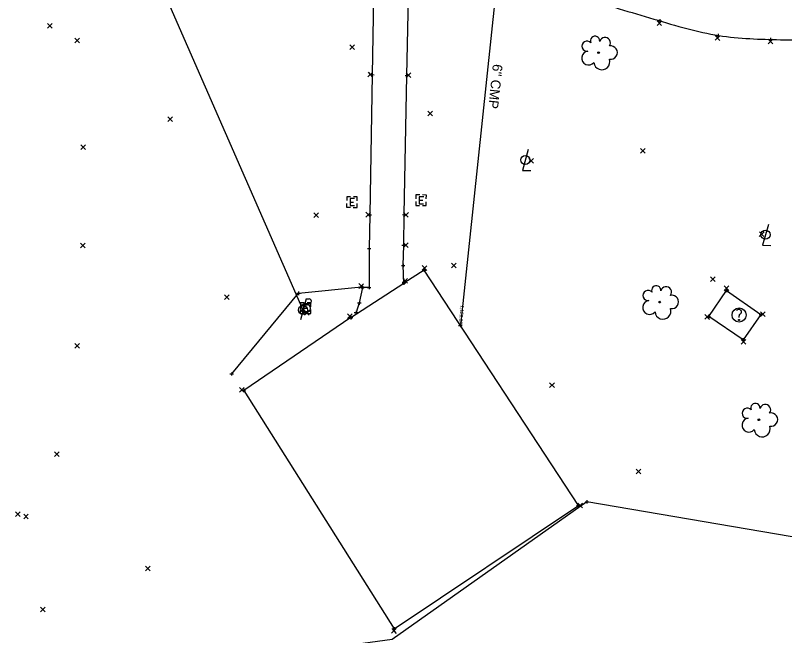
# Model space of a CAD drawing. Extents: x 142461 to 147261, y 511126 to 514697.
# Drawn here: x 144942.1 to 145161.9, y 512719.1 to 512896.1 of the extents above; entities that cross this region are included whole.
import ezdxf

# ---------------------------------------------------------------- set-up
doc = ezdxf.new("R2010")
doc.units = 0
for name, color, linetype in [('DR_X_Elev_Flow', 7, 'Continuous'), ('GT_X_Rock_Outcrop', 7, 'Continuous'), ('LT_X_Poles', 7, 'Continuous'), ('PV_X_Walk', 7, 'Continuous'), ('RD_X_Concrete_Pad', 7, 'Continuous'), ('RD_X_Fence', 7, 'Continuous'), ('RD_X_Gate', 7, 'Continuous'), ('RD_X_Misc_Items', 7, 'Continuous'), ('SC_Scratch1', 7, 'Continuous'), ('SV_X_Random_Point', 7, 'Continuous'), ('SV_X_Shot_Marker', 7, 'Continuous'), ('UT_X_Electric', 7, 'Continuous'), ('UT_X_Electric_Cells', 7, 'Continuous'), ('UT_X_Sanitary_Line', 7, 'Continuous'), ('UT_X_Sanitary_Text', 7, 'Continuous'), ('VG_X_Cells', 7, 'Continuous'), ('VG_X_Tree_Line_Rt', 7, 'Continuous')]:
    doc.layers.add(name, color=color, linetype=linetype)

msp = doc.modelspace()

# ---------------------------------------------------------------- linework, layer by layer
at = {"layer": 'DR_X_Elev_Flow'}
for p, q in [((145069.22, 512808.09), (145069.22, 512807.09)), ((145068.72, 512807.59), (145069.72, 512807.59)), ((145069.22, 512807.59), (145069.22, 512807.59))]:
    msp.add_line(p, q, dxfattribs=at)
at = {"layer": 'GT_X_Rock_Outcrop'}
msp.add_lwpolyline([(145003.89, 512793.77), (145023.02, 512816.77), (145041.01, 512818.64)], dxfattribs=at)
at = {"layer": 'LT_X_Poles'}
for points in [[(145088.61, 512857.79), (145086.97, 512851.82), (145089.34, 512851.8)], [(145157.21, 512836.44), (145155.58, 512830.48), (145157.94, 512830.45)]]:
    msp.add_lwpolyline(points, dxfattribs=at)
for centre in [(145087.79, 512854.84), (145156.4, 512833.5)]:
    msp.add_circle(centre, 1.3, dxfattribs=at)
at = {"layer": 'PV_X_Walk'}
for p, q in [((145044.7, 512919.18), (145044.06, 512879.19)), ((145053.92, 512878.99), (145054.78, 512918.79)), ((145044.06, 512879.19), (145043.35, 512839.22)), ((145053.18, 512839.23), (145053.92, 512878.99)), ((145043.35, 512839.22), (145043.15, 512829.53)), ((145053.03, 512830.54), (145053.18, 512839.23)), ((145052.88, 512824.7), (145053.03, 512830.54)), ((145043.15, 512829.53), (145043.14, 512818.41)), ((145053.1, 512819.92), (145052.88, 512824.7)), ((145041.24, 512818.45), (145040.36, 512814.02)), ((145043.14, 512818.41), (145041.24, 512818.45)), ((145040.36, 512814.02), (145039.41, 512811.27))]:
    msp.add_line(p, q, dxfattribs=at)
msp.add_open_spline([(145063.98, 512925.11), (145069.77, 512919.92), (145080.69, 512909.67), (145103.07, 512901.33), (145123.63, 512895.37), (145142.03, 512889.72), (145159.63, 512889.13), (145176.81, 512888.85), (145194, 512889.65), (145209.87, 512893.18), (145224.9, 512894.34), (145240.29, 512892.09), (145248.15, 512887), (145251.76, 512882.95)], degree=3, dxfattribs=at)
at = {"layer": 'RD_X_Concrete_Pad'}
msp.add_lwpolyline([(145140.22, 512810.19), (145145.29, 512817.62), (145155.1, 512810.72), (145150.05, 512803.47)], close=True, dxfattribs=at)
at = {"layer": 'RD_X_Fence'}
msp.add_lwpolyline([(145037.96, 512809.83), (145007.33, 512789.05), (145050.33, 512720.98), (145102.93, 512756.21), (145058.85, 512823.41), (145053.07, 512819.65)], dxfattribs=at)
at = {"layer": 'RD_X_Gate'}
msp.add_lwpolyline([(145037.96, 512809.83), (145053.07, 512819.65)], dxfattribs=at)
at = {"layer": 'RD_X_Misc_Items'}
msp.add_line((145148.83, 512809.82), (145148.83, 512810.3), dxfattribs=at)
for centre, radius in [((145148.84, 512810.58), 2), ((145148.82, 512809.17), 0.17)]:
    msp.add_circle(centre, radius, dxfattribs=at)
for centre, radius, start, end in [((145148.78, 512811.39), 0.754, 87.7326, 151.9471), ((145148.83, 512811.46), 0.688, 291.3416, 91.867), ((145149.42, 512810.34), 0.587, 124.8704, 183.4915)]:
    msp.add_arc(centre, radius, start, end, dxfattribs=at)
at = {"layer": 'SV_X_Random_Point'}
for p, q in [((144951.24, 512892.43), (144952.57, 512893.76)), ((144951.24, 512893.76), (144952.57, 512892.43)), ((145125.4, 512893.26), (145126.75, 512894.58)), ((145125.42, 512894.59), (145126.73, 512893.24)), ((144959.06, 512888.25), (144960.4, 512889.59)), ((144959.06, 512889.59), (144960.4, 512888.25)), ((145142.05, 512888.99), (145143.39, 512890.31)), ((145142.06, 512890.32), (145143.38, 512888.97)), ((145157.18, 512887.98), (145158.52, 512889.3)), ((145157.19, 512889.31), (145158.51, 512887.96)), ((145037.68, 512886.39), (145039.02, 512887.72)), ((145037.68, 512887.72), (145039.02, 512886.39)), ((145042.82, 512878.53), (145044.17, 512879.85)), ((145042.84, 512879.86), (145044.16, 512878.51)), ((145053.75, 512878.37), (145055.1, 512879.69)), ((145053.77, 512879.7), (145055.09, 512878.35)), ((144985.63, 512865.8), (144986.96, 512867.14)), ((144985.63, 512867.14), (144986.96, 512865.8)), ((145059.9, 512867.45), (145061.24, 512868.79)), ((145059.9, 512868.79), (145061.24, 512867.45)), ((144960.8, 512857.84), (144962.13, 512859.18)), ((144960.8, 512859.18), (144962.13, 512857.84)), ((145120.67, 512856.79), (145122.01, 512858.12)), ((145120.67, 512858.12), (145122.01, 512856.79)), ((145088.8, 512853.94), (145090.14, 512855.26)), ((145088.81, 512855.28), (145090.13, 512853.93)), ((145027.36, 512838.4), (145028.69, 512839.74)), ((145027.36, 512839.74), (145028.69, 512838.4)), ((145042.21, 512838.55), (145043.55, 512839.87)), ((145042.22, 512839.89), (145043.54, 512838.54)), ((145053.01, 512838.48), (145054.36, 512839.81)), ((145053.02, 512839.82), (145054.34, 512838.47)), ((145154.62, 512832.99), (145155.97, 512834.31)), ((145154.64, 512834.32), (145155.96, 512832.97)), ((144960.72, 512829.76), (144962.05, 512831.1)), ((144960.72, 512831.1), (144962.05, 512829.76)), ((145052.94, 512829.85), (145054.29, 512831.17)), ((145052.95, 512831.19), (145054.27, 512829.84)), ((145058.27, 512823.34), (145059.61, 512824.66)), ((145058.28, 512824.67), (145059.6, 512823.33)), ((145066.68, 512824.01), (145068.01, 512825.34)), ((145066.68, 512825.34), (145068.01, 512824.01)), ((145052.78, 512819.7), (145054.12, 512821.03)), ((145052.79, 512821.04), (145054.11, 512819.69)), ((145140.67, 512820.19), (145142, 512821.52)), ((145140.67, 512821.52), (145142, 512820.19)), ((145040.18, 512818.19), (145041.53, 512819.51)), ((145040.2, 512819.53), (145041.52, 512818.18)), ((145144.57, 512817.55), (145145.92, 512818.87)), ((145144.59, 512818.88), (145145.91, 512817.53)), ((145001.88, 512815.05), (145003.21, 512816.38)), ((145001.88, 512816.38), (145003.21, 512815.05)), ((145024.69, 512810.5), (145026.04, 512811.82)), ((145024.71, 512811.84), (145026.03, 512810.49)), ((145037, 512809.61), (145038.35, 512810.93)), ((145037.01, 512810.94), (145038.33, 512809.6)), ((145139.07, 512809.36), (145140.42, 512810.68)), ((145139.09, 512810.69), (145140.4, 512809.34)), ((145154.93, 512810.13), (145156.28, 512811.45)), ((145154.94, 512811.47), (145156.26, 512810.12)), ((145149.44, 512802.28), (145150.79, 512803.6)), ((145149.45, 512803.61), (145150.77, 512802.26)), ((144959.08, 512801.11), (144960.42, 512802.44)), ((144959.08, 512802.44), (144960.42, 512801.11)), ((145094.73, 512789.89), (145096.07, 512791.22)), ((145094.73, 512791.22), (145096.07, 512789.89)), ((145006.11, 512788.59), (145007.45, 512789.91)), ((145006.12, 512789.93), (145007.44, 512788.58)), ((144953.27, 512770.21), (144954.61, 512771.55)), ((144953.27, 512771.55), (144954.61, 512770.21)), ((145119.48, 512765.2), (145120.81, 512766.53)), ((145119.48, 512766.53), (145120.81, 512765.2)), ((145102.78, 512755.52), (145104.12, 512756.84)), ((145102.79, 512756.85), (145104.11, 512755.5)), ((144942.1, 512753.06), (144943.44, 512754.39)), ((144942.1, 512754.39), (144943.44, 512753.06)), ((144944.47, 512752.42), (144945.8, 512753.75)), ((144944.47, 512753.75), (144945.8, 512752.42)), ((144979.23, 512737.51), (144980.56, 512738.85)), ((144979.23, 512738.85), (144980.56, 512737.51)), ((144949.24, 512725.87), (144950.57, 512727.2)), ((144949.24, 512727.2), (144950.57, 512725.87)), ((145049.58, 512719.72), (145050.93, 512721.05)), ((145049.6, 512721.06), (145050.92, 512719.71))]:
    msp.add_line(p, q, dxfattribs=at)
at = {"layer": 'SV_X_Shot_Marker'}
for p, q in [((145125.73, 512894.54), (145126.73, 512894.53)), ((145126.24, 512895.03), (145126.23, 512894.03)), ((145126.23, 512894.53), (145126.23, 512894.53)), ((145142.34, 512890.31), (145143.34, 512890.3)), ((145142.84, 512890.81), (145142.83, 512889.81)), ((145142.84, 512890.31), (145142.84, 512890.31)), ((145157.3, 512889.24), (145158.3, 512889.23)), ((145157.81, 512889.73), (145157.8, 512888.73)), ((145157.8, 512889.23), (145157.8, 512889.23)), ((145043.56, 512879.19), (145044.56, 512879.18)), ((145044.07, 512879.69), (145044.06, 512878.69)), ((145044.06, 512879.19), (145044.06, 512879.19)), ((145053.42, 512878.99), (145054.42, 512878.98)), ((145053.93, 512879.49), (145053.92, 512878.49)), ((145053.92, 512878.99), (145053.92, 512878.99)), ((145042.85, 512839.22), (145043.85, 512839.21)), ((145043.35, 512839.72), (145043.34, 512838.72)), ((145043.35, 512839.22), (145043.35, 512839.22)), ((145052.68, 512839.23), (145053.68, 512839.22)), ((145053.18, 512839.73), (145053.17, 512838.73)), ((145053.18, 512839.23), (145053.18, 512839.23)), ((145043.16, 512830.03), (145043.15, 512829.03)), ((145052.53, 512830.55), (145053.53, 512830.54)), ((145053.04, 512831.04), (145053.03, 512830.04)), ((145053.03, 512830.54), (145053.03, 512830.54)), ((145042.65, 512829.53), (145043.65, 512829.52)), ((145043.15, 512829.53), (145043.15, 512829.53)), ((145052.38, 512824.71), (145053.38, 512824.7)), ((145052.88, 512825.2), (145052.87, 512824.2)), ((145052.88, 512824.7), (145052.88, 512824.7)), ((145058.35, 512823.41), (145059.35, 512823.4)), ((145058.85, 512823.91), (145058.84, 512822.91)), ((145058.85, 512823.41), (145058.85, 512823.41)), ((145041.02, 512819.14), (145041.01, 512818.14)), ((145041.24, 512818.95), (145041.23, 512817.95)), ((145043.15, 512818.91), (145043.14, 512817.91)), ((145052.57, 512819.66), (145053.57, 512819.65)), ((145052.6, 512819.93), (145053.6, 512819.92)), ((145053.08, 512820.15), (145053.07, 512819.15)), ((145053.07, 512819.65), (145053.07, 512819.65)), ((145053.11, 512820.42), (145053.1, 512819.42)), ((145053.1, 512819.92), (145053.1, 512819.92)), ((145022.52, 512816.78), (145023.52, 512816.77)), ((145023.02, 512817.27), (145023.01, 512816.27)), ((145023.02, 512816.77), (145023.02, 512816.77)), ((145040.51, 512818.65), (145041.51, 512818.64)), ((145040.74, 512818.45), (145041.74, 512818.44)), ((145041.01, 512818.64), (145041.01, 512818.64)), ((145041.24, 512818.45), (145041.24, 512818.45)), ((145042.64, 512818.41), (145043.64, 512818.4)), ((145043.14, 512818.41), (145043.14, 512818.41)), ((145144.79, 512817.62), (145145.79, 512817.61)), ((145145.3, 512818.12), (145145.29, 512817.12)), ((145145.29, 512817.62), (145145.29, 512817.62)), ((145040.37, 512814.52), (145040.36, 512813.52)), ((145024.3, 512812.48), (145024.29, 512811.48)), ((145039.86, 512814.02), (145040.86, 512814.01)), ((145040.36, 512814.02), (145040.36, 512814.02)), ((145023.8, 512811.98), (145024.8, 512811.97)), ((145024.3, 512811.98), (145024.3, 512811.98)), ((145037.97, 512810.33), (145037.96, 512809.33)), ((145038.91, 512811.27), (145039.91, 512811.26)), ((145039.41, 512811.77), (145039.4, 512810.77)), ((145039.41, 512811.27), (145039.41, 512811.27)), ((145139.72, 512810.2), (145140.72, 512810.19)), ((145140.22, 512810.69), (145140.21, 512809.69)), ((145140.22, 512810.19), (145140.22, 512810.19)), ((145154.6, 512810.72), (145155.6, 512810.71)), ((145155.11, 512811.22), (145155.1, 512810.22)), ((145155.1, 512810.72), (145155.1, 512810.72)), ((145037.46, 512809.84), (145038.46, 512809.83)), ((145037.96, 512809.83), (145037.96, 512809.83)), ((145149.55, 512803.48), (145150.55, 512803.47)), ((145150.05, 512803.97), (145150.04, 512802.97)), ((145150.05, 512803.47), (145150.05, 512803.47)), ((145003.39, 512793.77), (145004.39, 512793.76)), ((145003.89, 512794.27), (145003.88, 512793.27)), ((145003.89, 512793.77), (145003.89, 512793.77)), ((145006.83, 512789.06), (145007.83, 512789.05)), ((145007.33, 512789.55), (145007.32, 512788.55)), ((145007.33, 512789.05), (145007.33, 512789.05)), ((145104.84, 512757.26), (145105.84, 512757.26)), ((145105.34, 512757.76), (145105.34, 512756.76)), ((145105.34, 512757.26), (145105.34, 512757.26)), ((145102.43, 512756.21), (145103.43, 512756.2)), ((145102.94, 512756.71), (145102.93, 512755.71)), ((145102.93, 512756.21), (145102.93, 512756.21)), ((145049.83, 512720.99), (145050.83, 512720.98)), ((145050.34, 512721.48), (145050.33, 512720.48)), ((145050.33, 512720.98), (145050.33, 512720.98))]:
    msp.add_line(p, q, dxfattribs=at)
at = {"layer": 'UT_X_Electric'}
msp.add_lwpolyline([(145024.3, 512811.98), (144963.47, 512950.87)], dxfattribs=at)
at = {"layer": 'UT_X_Electric_Cells'}
for p, q in [((145057.49, 512843.35), (145058.49, 512843.34)), ((145057.99, 512843.35), (145057.99, 512843.35)), ((145037.74, 512842.82), (145038.74, 512842.81)), ((145038.24, 512842.82), (145038.24, 512842.82)), ((145025.19, 512815.17), (145023.52, 512809.19)), ((145025.19, 512815.17), (145026.04, 512815.16)), ((145024.44, 512812.53), (145025.34, 512812.52)), ((145024.83, 512813.9), (145026.02, 512813.88)), ((145025, 512812.52), (145025, 512812.52))]:
    msp.add_line(p, q, dxfattribs=at)
for points in [[(145037.86, 512844.32), (145036.76, 512844.33), (145036.75, 512843.23)], [(145039, 512843.81), (145037.75, 512843.82), (145037.73, 512841.82), (145038.98, 512841.81)], [(145039.75, 512843.2), (145039.76, 512844.3), (145038.66, 512844.31)], [(145056.49, 512842.96), (145056.48, 512841.86), (145057.58, 512841.85)], [(145057.61, 512844.85), (145056.51, 512844.86), (145056.49, 512843.76)], [(145058.75, 512844.34), (145057.5, 512844.35), (145057.48, 512842.35), (145058.73, 512842.34)], [(145059.49, 512843.73), (145059.51, 512844.83), (145058.41, 512844.85)], [(145036.74, 512842.43), (145036.73, 512841.33), (145037.83, 512841.32)], [(145038.63, 512841.31), (145039.73, 512841.3), (145039.74, 512842.4)], [(145058.38, 512841.85), (145059.48, 512841.83), (145059.49, 512842.93)], [(145024.62, 512814.03), (145023.52, 512814.04), (145023.51, 512812.94)], [(145025.57, 512813.42), (145024.45, 512813.43), (145024.43, 512811.63), (145025.55, 512811.62)], [(145026.51, 512812.91), (145026.52, 512814.01), (145025.42, 512814.02)], [(145023.5, 512812.14), (145023.49, 512811.04), (145024.59, 512811.03)], [(145025.39, 512811.02), (145026.49, 512811.01), (145026.5, 512812.11)]]:
    msp.add_lwpolyline(points, dxfattribs=at)
for centre, radius in [((145024.3, 512811.98), 1.3), ((145025, 512812.52), 1.35)]:
    msp.add_circle(centre, radius, dxfattribs=at)
msp.add_arc((145026.04, 512814.52), 0.638, 268.2853, 90.5319, dxfattribs=at)
at = {"layer": 'UT_X_Sanitary_Line'}
msp.add_line((145083.77, 512944.38), (145069.22, 512807.59), dxfattribs=at)
at = {"layer": 'VG_X_Cells'}
for centre in [(145108.71, 512885.46), (145126.17, 512814.27), (145154.5, 512780.68)]:
    msp.add_circle(centre, 0.24, dxfattribs=at)
for centre, radius, start, end in [((145107.72, 512888.83), 1.32, 354.0047, 205.9741), ((145110.53, 512888.29), 1.55, 323.83, 165.0376), ((145105.4, 512887.32), 1.47, 39.0625, 279.5412), ((145112.17, 512885.5), 1.91, 259.1453, 101.4596), ((145105.85, 512883.91), 1.97, 96.1722, 320.5737), ((145109.65, 512882.85), 2.28, 184.9476, 19.4572), ((145125.18, 512817.64), 1.32, 354.0047, 205.9741), ((145122.86, 512816.14), 1.47, 39.0625, 279.5412), ((145127.99, 512817.1), 1.55, 323.83, 165.0376), ((145123.31, 512812.72), 1.97, 96.1722, 320.5737), ((145129.63, 512814.31), 1.91, 259.1453, 101.4596), ((145127.11, 512811.67), 2.28, 184.9476, 19.4572), ((145151.19, 512782.54), 1.47, 39.0625, 279.5412), ((145153.52, 512784.05), 1.32, 354.0047, 205.9741), ((145156.33, 512783.51), 1.55, 323.83, 165.0376), ((145157.96, 512780.72), 1.91, 259.1453, 101.4596), ((145151.65, 512779.13), 1.97, 96.1722, 320.5737), ((145155.45, 512778.07), 2.28, 184.9476, 19.4572)]:
    msp.add_arc(centre, radius, start, end, dxfattribs=at)
at = {"layer": 'VG_X_Tree_Line_Rt'}
msp.add_lwpolyline([(146947.66, 514356.52), (145717.97, 513531.12), (145371.07, 513226.4), (145377.36, 513214.09), (145451.54, 513178.28), (145503.58, 513133.27), (145545.91, 513109.97), (145608.82, 513056.73), (145605.74, 513033.91), (145581.95, 513002.11), (145555.75, 512960.91), (145522.34, 512932.07), (145469.09, 512903.96), (145424.74, 512872.58), (145381.48, 512852.38), (145321.04, 512823.39), (145281.26, 512801.98), (145242.36, 512776.09), (145202.57, 512754.4), (145176.31, 512745.17), (145105.34, 512757.26), (145049.76, 512717.92), (145016.26, 512713.4), (144997.12, 512524.34)], dxfattribs=at)

# ---------------------------------------------------------------- texts
at = {"layer": 'SC_Scratch1'}
msp.add_text("1,120.29'", height=1, rotation=263.9289, dxfattribs=at).set_placement((145069.34, 512813.39))
at = {"layer": 'UT_X_Sanitary_Text'}
msp.add_text('6" CMP', height=2.8, rotation=263.9289, dxfattribs=at).set_placement((145078.53, 512882.31))

doc.saveas('drawing.dxf')
